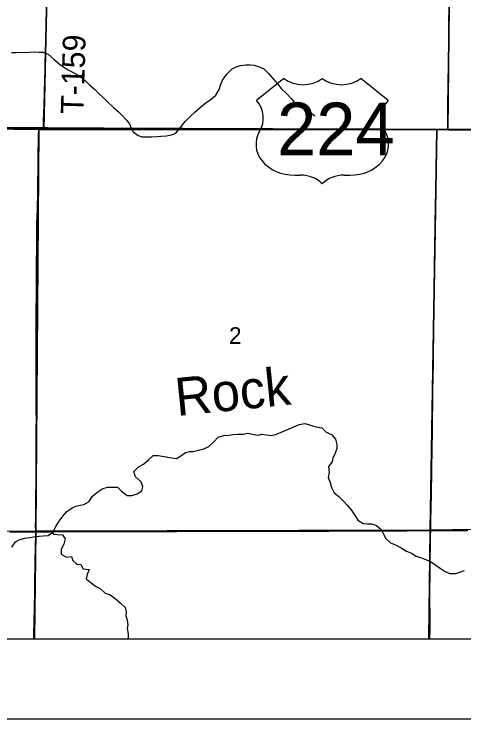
# Model space of a CAD drawing. Extents: x 0 to 34, y 0 to 22.
# Drawn here: x 5.687 to 6.249, y 14 to 14.881 of the extents above; entities that cross this region are included whole.
import ezdxf

# ---------------------------------------------------------------- set-up
doc = ezdxf.new("R2010")
doc.units = 0
for name, color, linetype in [('GM_X_Corporation', 7, 'Continuous'), ('GM_X_County_Road', 7, 'Continuous'), ('GM_X_Minor_River', 7, 'Continuous'), ('GM_X_Minor_River_Text', 7, 'Continuous'), ('GM_X_Section_Text', 7, 'Continuous'), ('GM_X_Township_Road', 7, 'Continuous'), ('GM_X_Township_Road_Text', 7, 'Continuous'), ('GM_X_US_Location', 7, 'Continuous'), ('GM_X_US_Route', 7, 'Continuous'), ('GM_X_US_Shield', 7, 'Continuous'), ('SH_Data', 7, 'Continuous')]:
    doc.layers.add(name, color=color, linetype=linetype)

msp = doc.modelspace()

# ---------------------------------------------------------------- linework, layer by layer
at = {"layer": 'GM_X_Corporation'}
for points in [[(2.1, 20.71973), (2.1, 14.1), (8.9, 14.1), (8.9, 20.77204)], [(6.26687, 14.73694), (6.23828, 14.73691), (6.22912, 14.73693), (6.21511, 14.73696), (6.18793, 14.73702), (6.15032, 14.73714), (6.09158, 14.73723), (6.04092, 14.73748), (6.01077, 14.73761), (5.98559, 14.73775), (5.89826, 14.73795), (5.87433, 14.73796), (5.84729, 14.7382), (5.82459, 14.73832), (5.7988, 14.73851), (5.76896, 14.73853), (5.72887, 14.73878), (5.72358, 14.73883), (5.71787, 14.73888), (5.66578, 14.73939)], [(6.26687, 14.73694), (6.23828, 14.73691), (6.22912, 14.73693), (6.21511, 14.73696), (6.18793, 14.73702), (6.15032, 14.73714), (6.09158, 14.73723), (6.04092, 14.73748), (6.01077, 14.73761), (5.98559, 14.73775), (5.89826, 14.73795), (5.87433, 14.73796), (5.84729, 14.7382), (5.82459, 14.73832), (5.7988, 14.73851), (5.76896, 14.73853), (5.72887, 14.73878), (5.72358, 14.73883), (5.71787, 14.73888), (5.66578, 14.73939)], [(3.69807, 14.1), (6.729, 14.1)]]:
    msp.add_lwpolyline(points, dxfattribs=at)
for points in [[(5.2282, 15.24475), (5.73533, 15.24166), (5.72426, 14.73698), (5.71782, 14.73702), (5.21872, 14.74348)], [(5.73533, 15.24166), (6.23441, 15.24275), (6.2292, 14.73651), (6.21537, 14.73679), (5.72426, 14.73698)], [(6.23441, 15.24275), (6.7363, 15.23833), (6.73624, 15.22867), (6.73321, 14.73756), (6.2292, 14.73651)], [(5.21872, 14.74348), (5.71782, 14.73702), (5.71415, 14.23456), (5.2152, 14.23041)], [(5.71782, 14.73702), (5.72426, 14.73698), (6.21537, 14.73679), (6.20716, 14.23587), (5.71415, 14.23456)], [(6.2292, 14.73651), (6.73321, 14.73756), (6.72845, 14.24383), (6.20716, 14.23587), (6.21537, 14.73679)], [(6.20525, 14.1), (6.728, 14.1), (6.72845, 14.24383), (6.20716, 14.23587)], [(5.21396, 14.1), (5.71255, 14.1), (5.71415, 14.23456), (5.2152, 14.23041)], [(5.71255, 14.1), (6.20525, 14.1), (6.20716, 14.23587), (5.71415, 14.23456)]]:
    msp.add_lwpolyline(points, close=True, dxfattribs=at)
at = {"layer": 'GM_X_County_Road'}
for points in [[(6.22923, 14.73665), (6.22922, 14.73754), (6.22917, 14.74984), (6.22931, 14.76287), (6.22967, 14.79702), (6.22992, 14.81596), (6.2304, 14.84981), (6.23058, 14.86503), (6.23091, 14.89486), (6.23122, 14.92377), (6.23163, 14.95017), (6.23197, 14.97222), (6.23228, 14.9921), (6.23268, 15.01414), (6.23307, 15.03962), (6.23339, 15.08437), (6.23347, 15.0996), (6.2342, 15.14373), (6.23445, 15.16331), (6.23468, 15.1922), (6.23488, 15.22826), (6.23506, 15.24161), (6.23508, 15.24316)], [(5.68191, 14.23347), (5.70376, 14.23377), (5.71403, 14.23388)], [(5.71403, 14.23388), (5.73194, 14.23402), (5.76531, 14.23411), (5.78321, 14.23416), (5.81466, 14.23437), (5.84062, 14.23442), (5.87167, 14.2345), (5.89046, 14.2345), (5.9026, 14.23454), (5.91875, 14.23457), (5.93896, 14.23462), (5.95481, 14.23473), (5.96665, 14.2347), (5.98318, 14.23471), (6.00121, 14.23471), (6.01648, 14.23472), (6.03163, 14.23478), (6.04572, 14.23491), (6.0645, 14.23479), (6.0804, 14.23479), (6.09772, 14.23502), (6.11302, 14.2351), (6.1293, 14.23518), (6.13933, 14.23512), (6.15331, 14.23508), (6.17786, 14.23515), (6.20777, 14.23537)], [(6.20777, 14.23537), (6.21081, 14.23539), (6.22447, 14.23545), (6.23191, 14.23552), (6.25427, 14.23572)]]:
    msp.add_lwpolyline(points, dxfattribs=at)
at = {"layer": 'GM_X_Minor_River'}
for points in [[(5.68387, 14.83303), (5.68975, 14.83301), (5.69621, 14.83355), (5.70095, 14.83334), (5.70703, 14.8337), (5.71196, 14.83387), (5.71822, 14.83346), (5.72316, 14.83344), (5.7296, 14.83113), (5.73679, 14.82465), (5.7434, 14.81893), (5.74908, 14.81492), (5.75476, 14.81148), (5.76252, 14.80746), (5.76783, 14.80459), (5.77596, 14.79811), (5.78144, 14.79258), (5.78768, 14.78724), (5.79354, 14.78153), (5.79846, 14.77676), (5.80413, 14.77104), (5.8115, 14.76437), (5.81679, 14.75998), (5.82114, 14.75522), (5.82737, 14.74855), (5.83115, 14.74379), (5.83322, 14.73866), (5.83604, 14.73391), (5.84229, 14.72952), (5.84702, 14.72779), (5.85253, 14.72757), (5.85936, 14.72755), (5.86582, 14.72809), (5.87056, 14.72845), (5.87721, 14.7288), (5.88423, 14.7301), (5.88937, 14.73216), (5.89452, 14.73916), (5.90082, 14.74673), (5.90672, 14.75277), (5.91282, 14.75863), (5.91949, 14.7643), (5.92711, 14.77053), (5.93301, 14.7743), (5.9391, 14.77997), (5.94331, 14.78697), (5.94485, 14.79209), (5.94753, 14.79872), (5.95288, 14.80609), (5.95974, 14.81252), (5.9645, 14.81515), (5.96963, 14.81684), (5.97703, 14.81757)], [(5.97703, 14.81757), (5.98216, 14.81774), (5.9869, 14.81734), (5.99316, 14.81541), (5.99903, 14.81292), (6.0047, 14.8072), (6.01055, 14.80073), (6.01641, 14.79406), (6.02094, 14.78797), (6.02737, 14.78187), (6.03322, 14.77558), (6.03738, 14.77044), (6.04324, 14.76548), (6.04949, 14.76299), (6.05706, 14.7584), (6.06293, 14.75402)], [(5.8282, 14.27914), (5.83465, 14.27949), (5.84074, 14.28136), (5.84683, 14.28532), (5.84799, 14.29025), (5.84593, 14.29633), (5.83893, 14.30243), (5.83687, 14.30927), (5.8424, 14.31531), (5.84868, 14.31832), (5.85497, 14.3238), (5.86106, 14.32946), (5.86733, 14.32944), (5.87207, 14.32828), (5.87719, 14.3275), (5.88364, 14.32652), (5.89009, 14.32574), (5.89541, 14.32894), (5.90112, 14.3329), (5.90625, 14.33421), (5.911, 14.33438), (5.91784, 14.33586), (5.9243, 14.33754), (5.93039, 14.34055), (5.93667, 14.3466), (5.94201, 14.35208), (5.94923, 14.35414), (5.9555, 14.35487), (5.96025, 14.35561), (5.96651, 14.35596), (5.97316, 14.35593), (5.97923, 14.35704), (5.98492, 14.35607), (5.99194, 14.35471), (5.99688, 14.35583), (6.00257, 14.35524), (6.00788, 14.35446), (6.01358, 14.35576), (6.02004, 14.3582), (6.02518, 14.36008), (6.03088, 14.36252), (6.03601, 14.36477), (6.04343, 14.36816), (6.05046, 14.36927), (6.0552, 14.36792), (6.06145, 14.36618), (6.06676, 14.36483), (6.0715, 14.36387), (6.07717, 14.35853), (6.08361, 14.35547), (6.08871, 14.34956), (6.09058, 14.34292), (6.09056, 14.33817), (6.08806, 14.33116), (6.08557, 14.32624), (6.0846, 14.3215), (6.08021, 14.31564), (6.08075, 14.30824), (6.07958, 14.3016), (6.08202, 14.29571), (6.08389, 14.28925), (6.08728, 14.2826), (6.09295, 14.27821), (6.09843, 14.27269), (6.10315, 14.26735), (6.10825, 14.26145), (6.1124, 14.25517), (6.11655, 14.24852), (6.12317, 14.2445), (6.12886, 14.24372), (6.13361, 14.24408), (6.14005, 14.24178), (6.14572, 14.23663), (6.14817, 14.23188), (6.15175, 14.2256), (6.15742, 14.22007), (6.16386, 14.21777), (6.17068, 14.21395), (6.17749, 14.20956), (6.18355, 14.20725), (6.18961, 14.20362), (6.19605, 14.20132), (6.2025, 14.19883), (6.20742, 14.19672), (6.21404, 14.19214), (6.21991, 14.18794), (6.22502, 14.18469), (6.23184, 14.18182), (6.23905, 14.18179), (6.24399, 14.18328), (6.25007, 14.18554)], [(5.68424, 14.21486), (5.68864, 14.22148), (5.69358, 14.22374), (5.70024, 14.22599), (5.70669, 14.22672), (5.71144, 14.22746), (5.71828, 14.22857), (5.7234, 14.22893), (5.72967, 14.22909), (5.73595, 14.23381), (5.7394, 14.24062), (5.74322, 14.24724), (5.74819, 14.25386), (5.75276, 14.25878), (5.75962, 14.26387), (5.76437, 14.26613), (5.7695, 14.26705), (5.77425, 14.26817), (5.78091, 14.27175), (5.78454, 14.27799), (5.79064, 14.28309), (5.79787, 14.28818), (5.80414, 14.28986), (5.81648, 14.28981), (5.8212, 14.28486), (5.8282, 14.27914)], [(5.735, 14.23309), (5.73632, 14.23096), (5.74106, 14.23075), (5.74751, 14.22996), (5.7511, 14.22521), (5.74917, 14.21838), (5.74592, 14.21214), (5.7457, 14.20607), (5.75251, 14.20224), (5.75878, 14.20298), (5.76028, 14.19823), (5.76538, 14.19365), (5.77031, 14.19306), (5.77352, 14.18755), (5.78073, 14.18676), (5.77823, 14.18051), (5.77726, 14.1752), (5.7835, 14.17024), (5.7888, 14.16605), (5.79448, 14.16318), (5.8009, 14.15727), (5.80716, 14.15516), (5.81302, 14.15096), (5.81964, 14.14524), (5.82569, 14.13933), (5.82699, 14.13383), (5.82678, 14.12889), (5.82846, 14.12357), (5.8292, 14.11769), (5.82842, 14.11295), (5.82972, 14.10631), (5.82951, 14.10156), (5.82919, 14.1)]]:
    msp.add_lwpolyline(points, dxfattribs=at)
at = {"layer": 'GM_X_Township_Road'}
msp.add_line((5.71798, 14.73861), (5.72369, 14.73855), dxfattribs=at)
for points in [[(5.72369, 14.73855), (5.72388, 14.74396), (5.72399, 14.74707), (5.72427, 14.75732), (5.72455, 14.76788), (5.72553, 14.79955), (5.72582, 14.81041), (5.72609, 14.82159), (5.72645, 14.83245), (5.72682, 14.84767), (5.72727, 14.86536), (5.72767, 14.87591), (5.72835, 14.89982), (5.72862, 14.91264)], [(5.71403, 14.23388), (5.71402, 14.24234), (5.71406, 14.24948), (5.71417, 14.26374), (5.71424, 14.2715), (5.7143, 14.2774), (5.71452, 14.29573), (5.71464, 14.31344), (5.71467, 14.33613), (5.71476, 14.35136), (5.71484, 14.36379), (5.71493, 14.37404), (5.71484, 14.38492), (5.71474, 14.39455), (5.71477, 14.40201), (5.71484, 14.44148), (5.71471, 14.48002), (5.71473, 14.48375), (5.71474, 14.49028), (5.71484, 14.51017), (5.71497, 14.53067), (5.71518, 14.55522), (5.71527, 14.56641), (5.71547, 14.59281), (5.71551, 14.6012), (5.71555, 14.61022), (5.71563, 14.61859), (5.71612, 14.63736), (5.71656, 14.65819), (5.71691, 14.67495), (5.71706, 14.68304), (5.71716, 14.69949), (5.71775, 14.72963), (5.71792, 14.73649), (5.71798, 14.73861)], [(6.20777, 14.23537), (6.20806, 14.24907), (6.20835, 14.26219), (6.20874, 14.28237), (6.20926, 14.30941), (6.20958, 14.34002), (6.20991, 14.35598), (6.2101, 14.37511), (6.21042, 14.39369), (6.21042, 14.41006), (6.21068, 14.42761), (6.21108, 14.4444), (6.21117, 14.45578), (6.21156, 14.4834), (6.21162, 14.48931), (6.21165, 14.49304), (6.21172, 14.49832), (6.21178, 14.50334), (6.21182, 14.50678), (6.21188, 14.5114), (6.21189, 14.51532), (6.21202, 14.53309), (6.21208, 14.5468), (6.21233, 14.55607), (6.21264, 14.57178), (6.21288, 14.58468), (6.21301, 14.59651), (6.21325, 14.60853), (6.2135, 14.62099), (6.21381, 14.63896), (6.21424, 14.66212), (6.21447, 14.67847), (6.21476, 14.69366), (6.2153, 14.72249), (6.21523, 14.73519), (6.21522, 14.73668)], [(5.71171, 14.1), (5.7119, 14.1078), (5.71214, 14.12023), (5.71249, 14.14074), (5.71282, 14.15628), (5.71307, 14.1687), (5.71358, 14.19615), (5.71397, 14.21679), (5.71404, 14.22929), (5.71403, 14.23388)], [(6.20673, 14.1), (6.20686, 14.11161), (6.20686, 14.12975), (6.20678, 14.14752), (6.20685, 14.16121), (6.20687, 14.17999), (6.20726, 14.19922), (6.20756, 14.21594), (6.20762, 14.22863), (6.20777, 14.23537)]]:
    msp.add_lwpolyline(points, dxfattribs=at)
at = {"layer": 'GM_X_US_Route'}
msp.add_line((5.71798, 14.73861), (5.72369, 14.73855), dxfattribs=at)
for points in [[(5.12614, 14.74493), (5.13694, 14.74484), (5.16367, 14.74461), (5.21813, 14.74392), (5.21961, 14.7439), (5.24198, 14.74362), (5.26063, 14.7435), (5.29543, 14.74315), (5.31905, 14.74292), (5.36847, 14.74249), (5.4011, 14.74219), (5.44337, 14.74173), (5.4645, 14.74148), (5.4819, 14.74135), (5.51205, 14.74099), (5.5509, 14.74057), (5.57701, 14.74025), (5.61399, 14.73977), (5.66589, 14.73911), (5.71798, 14.73861)], [(5.72369, 14.73855), (5.72898, 14.7385), (5.76907, 14.73826), (5.79891, 14.73823), (5.82471, 14.73805), (5.8474, 14.73792), (5.87444, 14.73768), (5.89837, 14.73768), (5.9857, 14.73748), (6.01088, 14.73734), (6.04103, 14.7372), (6.09169, 14.73696), (6.15043, 14.73687), (6.18804, 14.73675), (6.21522, 14.73668), (6.22923, 14.73665), (6.23839, 14.73663), (6.26698, 14.73666)]]:
    msp.add_lwpolyline(points, dxfattribs=at)
at = {"layer": 'GM_X_US_Shield'}
for p, q in [((6.0242, 14.80073), (5.98987, 14.77327)), ((6.15466, 14.77327), (6.12033, 14.80073)), ((6.03793, 14.67988), (6.0448, 14.67988)), ((6.09973, 14.67988), (6.1066, 14.67988))]:
    msp.add_line(p, q, dxfattribs=at)
for centre, major_axis, start_param, end_param in [((6.04823, 14.82035), (-0.03433, 0), 0.795399, 2.346194), ((6.0963, 14.82035), (-0.03433, 0), 0.795399, 2.346194), ((5.9505, 14.75121), (0.04807, 0), 5.838949, 6.894067), ((6.19404, 14.75121), (-0.04807, 0), 5.672304, 6.727422), ((6.0374, 14.71833), (0.04807, 0), 2.702327, 4.723529), ((6.10713, 14.71833), (-0.04807, 0), 1.559657, 3.580859), ((6.0448, 14.65242), (-0.03433, 0), 3.785094, 4.712389), ((6.09973, 14.65242), (-0.03433, 0), 4.712389, 5.639684)]:
    msp.add_ellipse(centre, major_axis=major_axis, ratio=0.8, start_param=start_param, end_param=end_param, dxfattribs=at)
at = {"layer": 'SH_Data'}
for p, q in [((2.1, 14.1), (8.9, 14.1)), ((2, 14), (9, 14))]:
    msp.add_line(p, q, dxfattribs=at)

# ---------------------------------------------------------------- texts
at = {"layer": 'GM_X_Minor_River_Text'}
msp.add_text('Rock', height=0.047368, rotation=5.74737, dxfattribs=at).set_placement((5.89065, 14.37864))
at = {"layer": 'GM_X_Section_Text'}
msp.add_text('2', height=0.02093, rotation=0.00001, dxfattribs=at).set_placement((5.95569, 14.46879))
at = {"layer": 'GM_X_Township_Road_Text'}
msp.add_text('T-159', height=0.028409, rotation=88.3486, dxfattribs=at).set_placement((5.77373, 14.75597))
at = {"layer": 'GM_X_US_Location'}
for s, p in [('0', (6.07232, 14.73751)), ('/', (6.07233, 14.73751))]:
    msp.add_text(s, height=0.0000947, dxfattribs=at).set_placement(p)
msp.add_text('224', height=0.0000947, rotation=0.00001, dxfattribs=at).set_placement((6.04319, 14.71791))
at = {"layer": 'GM_X_US_Shield'}
msp.add_text('224', height=0.065918, dxfattribs=at).set_placement((6.01569, 14.7046))

doc.saveas('drawing.dxf')
